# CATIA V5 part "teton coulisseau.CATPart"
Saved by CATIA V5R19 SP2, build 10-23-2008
Part number: teton coulisseau 2
Bounding box of the stored display mesh (mm): x -65 to -55, y 9.057 to 11.057, z -5.157 to -3.157
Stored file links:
  C:\Users\Thinkmotion2\Desktop\Pack 1\IAO_2010_1396_fvigouroux\vigouroux\vigouroux\teton coulisseau.CATPart
  C:\Users\Thinkmotion2\Desktop\Pack 1\IAO_2010_1396_fvigouroux\vigouroux\vigouroux\mecanisme IAO.CATProduct
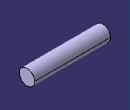
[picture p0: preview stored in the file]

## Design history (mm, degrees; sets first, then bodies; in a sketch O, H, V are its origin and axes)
Set1
  Plane1 to Plane3: linked copy from another document
  Point1: linked copy from another document
Body1 (main body)
  Sketch1 on Plane1, origin (-55, 0, 0), H (0, 1, 0), V (0, 0, 1)
    circle A1 centre (10.0575, -4.1575) radius 1
    point P1 (10.0575, -4.1575)
    reference projected point E1 (10.0575, -4.1575) from Point1
    radius A1 = 1
    distance P1 E1 = 0
  Pad1: profile Sketch1, direction (-1, 0, 0), length 10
